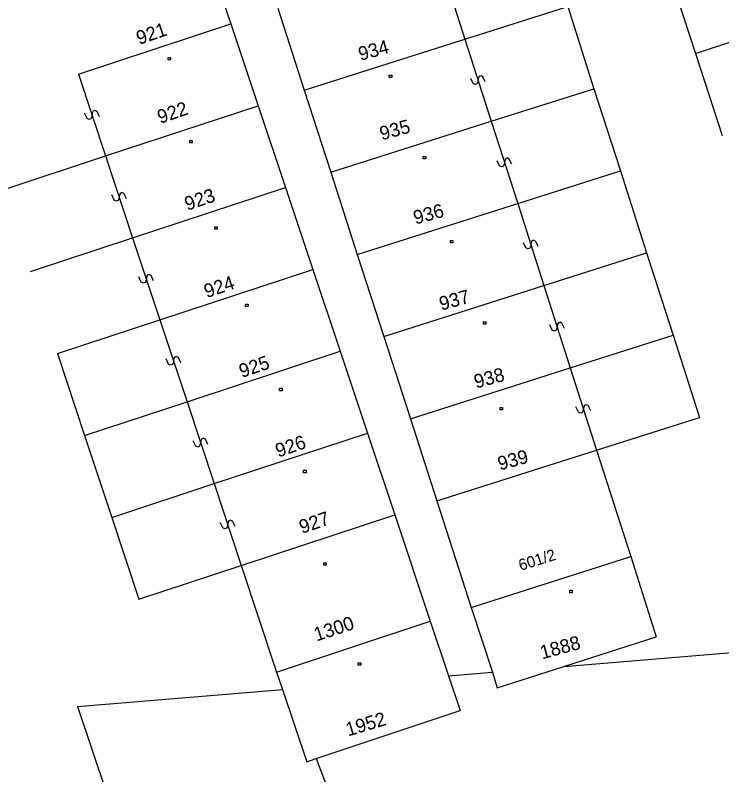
# Model space of a CAD drawing. Extents: x -493352 to -492964, y -1127001 to -1126712.
# Drawn here: x -493295.47 to -493269.27, y -1126768.92 to -1126740.75 of the extents above; entities that cross this region are included whole.
import ezdxf

# ---------------------------------------------------------------- set-up
doc = ezdxf.new("R2010")
doc.units = 0
doc.layers.add('katastrální mapa', color=7, linetype='Continuous')

msp = doc.modelspace()

# ---------------------------------------------------------------- linework, layer by layer
at = {"layer": 'katastrální mapa'}
for p, q in [((-493288.49, -1126738.04), (-493287.48, -1126741.07)), ((-493279.77, -1126738.59), (-493278.8, -1126741.64)), ((-493271.24, -1126739.13), (-493270.25, -1126742.17)), ((-493285.74, -1126740.49), (-493284.76, -1126743.54)), ((-493278.8, -1126741.64), (-493274.98, -1126740.43)), ((-493274.98, -1126740.43), (-493274.01, -1126743.48)), ((-493293.13, -1126742.94), (-493287.48, -1126741.07)), ((-493287.48, -1126741.07), (-493286.46, -1126744.11)), ((-493270.25, -1126742.17), (-493266.45, -1126740.91)), ((-493284.76, -1126743.54), (-493278.8, -1126741.64)), ((-493278.8, -1126741.64), (-493277.82, -1126744.69)), ((-493270.25, -1126742.17), (-493269.26, -1126745.21)), ((-493289.8, -1126742.32), (-493289.71, -1126742.32)), ((-493289.8, -1126742.41), (-493289.8, -1126742.32)), ((-493289.71, -1126742.41), (-493289.8, -1126742.41)), ((-493289.71, -1126742.32), (-493289.71, -1126742.41)), ((-493293.13, -1126742.94), (-493292.12, -1126745.97)), ((-493281.6, -1126742.98), (-493281.51, -1126742.98)), ((-493281.6, -1126743.07), (-493281.6, -1126742.98)), ((-493281.51, -1126743.07), (-493281.6, -1126743.07)), ((-493281.51, -1126742.98), (-493281.51, -1126743.07)), ((-493278.26, -1126743.02), (-493278.3, -1126743.1)), ((-493278.2, -1126743), (-493278.26, -1126743.02)), ((-493278.13, -1126743.04), (-493278.2, -1126743)), ((-493278.04, -1126743.23), (-493278.13, -1126743.04)), ((-493278.49, -1126743.29), (-493278.58, -1126743.1)), ((-493278.42, -1126743.33), (-493278.49, -1126743.29)), ((-493278.36, -1126743.31), (-493278.42, -1126743.33)), ((-493278.32, -1126743.23), (-493278.36, -1126743.31)), ((-493278.3, -1126743.1), (-493278.32, -1126743.23)), ((-493284.76, -1126743.54), (-493283.77, -1126746.58)), ((-493277.82, -1126744.69), (-493274.01, -1126743.48)), ((-493274.01, -1126743.48), (-493273.03, -1126746.53)), ((-493292.12, -1126745.97), (-493286.46, -1126744.11)), ((-493286.46, -1126744.11), (-493285.45, -1126747.14)), ((-493292.81, -1126744.58), (-493292.9, -1126744.39)), ((-493292.62, -1126744.39), (-493292.63, -1126744.52)), ((-493292.58, -1126744.31), (-493292.62, -1126744.39)), ((-493292.52, -1126744.29), (-493292.58, -1126744.31)), ((-493292.44, -1126744.33), (-493292.52, -1126744.29)), ((-493292.35, -1126744.52), (-493292.44, -1126744.33)), ((-493292.73, -1126744.62), (-493292.81, -1126744.58)), ((-493292.67, -1126744.6), (-493292.73, -1126744.62)), ((-493292.63, -1126744.52), (-493292.67, -1126744.6)), ((-493283.77, -1126746.58), (-493277.82, -1126744.69)), ((-493277.82, -1126744.69), (-493276.84, -1126747.74)), ((-493289, -1126745.4), (-493288.91, -1126745.4)), ((-493289, -1126745.49), (-493289, -1126745.4)), ((-493288.91, -1126745.49), (-493289, -1126745.49)), ((-493288.91, -1126745.4), (-493288.91, -1126745.49)), ((-493295.92, -1126747.23), (-493292.12, -1126745.97)), ((-493292.12, -1126745.97), (-493291.12, -1126749.01)), ((-493280.34, -1126745.99), (-493280.25, -1126745.99)), ((-493280.34, -1126746.08), (-493280.34, -1126745.99)), ((-493280.25, -1126746.08), (-493280.34, -1126746.08)), ((-493280.25, -1126745.99), (-493280.25, -1126746.08)), ((-493277.51, -1126746.34), (-493277.6, -1126746.15)), ((-493277.32, -1126746.15), (-493277.34, -1126746.28)), ((-493277.28, -1126746.07), (-493277.32, -1126746.15)), ((-493277.22, -1126746.05), (-493277.28, -1126746.07)), ((-493277.15, -1126746.09), (-493277.22, -1126746.05)), ((-493277.06, -1126746.28), (-493277.15, -1126746.09)), ((-493277.44, -1126746.38), (-493277.51, -1126746.34)), ((-493277.38, -1126746.36), (-493277.44, -1126746.38)), ((-493277.34, -1126746.28), (-493277.38, -1126746.36)), ((-493283.77, -1126746.58), (-493282.79, -1126749.63)), ((-493276.84, -1126747.74), (-493273.03, -1126746.53)), ((-493273.03, -1126746.53), (-493272.06, -1126749.57)), ((-493291.12, -1126749.01), (-493285.45, -1126747.14)), ((-493285.45, -1126747.14), (-493284.44, -1126750.18)), ((-493291.8, -1126747.61), (-493291.89, -1126747.42)), ((-493291.63, -1126747.56), (-493291.67, -1126747.63)), ((-493291.61, -1126747.42), (-493291.63, -1126747.56)), ((-493291.57, -1126747.35), (-493291.61, -1126747.42)), ((-493291.52, -1126747.33), (-493291.57, -1126747.35)), ((-493291.44, -1126747.37), (-493291.52, -1126747.33)), ((-493291.35, -1126747.56), (-493291.44, -1126747.37)), ((-493291.72, -1126747.65), (-493291.8, -1126747.61)), ((-493291.67, -1126747.63), (-493291.72, -1126747.65)), ((-493282.79, -1126749.63), (-493276.84, -1126747.74)), ((-493276.84, -1126747.74), (-493275.87, -1126750.78)), ((-493288.07, -1126748.6), (-493287.98, -1126748.6)), ((-493288.07, -1126748.69), (-493288.07, -1126748.6)), ((-493287.98, -1126748.69), (-493288.07, -1126748.69)), ((-493287.98, -1126748.6), (-493287.98, -1126748.69)), ((-493294.91, -1126750.26), (-493291.12, -1126749.01)), ((-493291.12, -1126749.01), (-493290.11, -1126752.05)), ((-493279.33, -1126749.11), (-493279.24, -1126749.11)), ((-493279.33, -1126749.2), (-493279.33, -1126749.11)), ((-493279.24, -1126749.2), (-493279.33, -1126749.2)), ((-493279.24, -1126749.11), (-493279.24, -1126749.2)), ((-493276.54, -1126749.38), (-493276.63, -1126749.19)), ((-493276.34, -1126749.19), (-493276.37, -1126749.33)), ((-493276.31, -1126749.12), (-493276.34, -1126749.19)), ((-493276.25, -1126749.1), (-493276.31, -1126749.12)), ((-493276.17, -1126749.14), (-493276.25, -1126749.1)), ((-493276.08, -1126749.33), (-493276.17, -1126749.14)), ((-493276.46, -1126749.42), (-493276.54, -1126749.38)), ((-493276.4, -1126749.4), (-493276.46, -1126749.42)), ((-493276.37, -1126749.33), (-493276.4, -1126749.4)), ((-493282.79, -1126749.63), (-493281.8, -1126752.67)), ((-493275.87, -1126750.78), (-493272.06, -1126749.57)), ((-493272.06, -1126749.57), (-493271.08, -1126752.62)), ((-493290.57, -1126750.39), (-493290.61, -1126750.46)), ((-493290.51, -1126750.37), (-493290.57, -1126750.39)), ((-493290.43, -1126750.41), (-493290.51, -1126750.37)), ((-493290.11, -1126752.05), (-493284.44, -1126750.18)), ((-493284.44, -1126750.18), (-493283.42, -1126753.21)), ((-493290.8, -1126750.65), (-493290.89, -1126750.46)), ((-493290.72, -1126750.69), (-493290.8, -1126750.65)), ((-493290.66, -1126750.67), (-493290.72, -1126750.69)), ((-493290.62, -1126750.6), (-493290.66, -1126750.67)), ((-493290.61, -1126750.46), (-493290.62, -1126750.6)), ((-493290.34, -1126750.6), (-493290.43, -1126750.41)), ((-493281.8, -1126752.67), (-493275.87, -1126750.78)), ((-493275.87, -1126750.78), (-493274.89, -1126753.83)), ((-493286.93, -1126751.47), (-493286.84, -1126751.47)), ((-493286.93, -1126751.56), (-493286.93, -1126751.47)), ((-493286.84, -1126751.47), (-493286.84, -1126751.56)), ((-493286.84, -1126751.56), (-493286.93, -1126751.56)), ((-493293.91, -1126753.3), (-493290.11, -1126752.05)), ((-493290.11, -1126752.05), (-493289.1, -1126755.09)), ((-493278.11, -1126752.12), (-493278.02, -1126752.12)), ((-493278.11, -1126752.21), (-493278.11, -1126752.12)), ((-493278.02, -1126752.21), (-493278.11, -1126752.21)), ((-493278.02, -1126752.12), (-493278.02, -1126752.21)), ((-493275.56, -1126752.43), (-493275.65, -1126752.24)), ((-493275.39, -1126752.37), (-493275.43, -1126752.45)), ((-493275.37, -1126752.24), (-493275.39, -1126752.37)), ((-493275.33, -1126752.16), (-493275.37, -1126752.24)), ((-493275.27, -1126752.14), (-493275.33, -1126752.16)), ((-493275.2, -1126752.18), (-493275.27, -1126752.14)), ((-493275.11, -1126752.37), (-493275.2, -1126752.18)), ((-493275.49, -1126752.47), (-493275.56, -1126752.43)), ((-493275.43, -1126752.45), (-493275.49, -1126752.47)), ((-493274.89, -1126753.83), (-493271.08, -1126752.62)), ((-493271.08, -1126752.62), (-493270.1, -1126755.67)), ((-493281.8, -1126752.67), (-493280.82, -1126755.72)), ((-493289.1, -1126755.09), (-493283.42, -1126753.21)), ((-493283.42, -1126753.21), (-493282.41, -1126756.25)), ((-493293.91, -1126753.3), (-493292.9, -1126756.34)), ((-493289.56, -1126753.43), (-493289.6, -1126753.5)), ((-493289.5, -1126753.41), (-493289.56, -1126753.43)), ((-493289.42, -1126753.45), (-493289.5, -1126753.41)), ((-493289.33, -1126753.64), (-493289.42, -1126753.45)), ((-493289.79, -1126753.69), (-493289.88, -1126753.5)), ((-493289.71, -1126753.73), (-493289.79, -1126753.69)), ((-493289.65, -1126753.71), (-493289.71, -1126753.73)), ((-493289.61, -1126753.64), (-493289.65, -1126753.71)), ((-493289.6, -1126753.5), (-493289.61, -1126753.64)), ((-493280.82, -1126755.72), (-493274.89, -1126753.83)), ((-493274.89, -1126753.83), (-493273.92, -1126756.88)), ((-493285.67, -1126754.59), (-493285.58, -1126754.59)), ((-493285.67, -1126754.68), (-493285.67, -1126754.59)), ((-493285.58, -1126754.59), (-493285.58, -1126754.68)), ((-493285.58, -1126754.68), (-493285.67, -1126754.68)), ((-493292.9, -1126756.34), (-493289.1, -1126755.09)), ((-493289.1, -1126755.09), (-493288.1, -1126758.12)), ((-493277.49, -1126755.3), (-493277.4, -1126755.3)), ((-493277.49, -1126755.39), (-493277.49, -1126755.3)), ((-493277.4, -1126755.39), (-493277.49, -1126755.39)), ((-493277.4, -1126755.3), (-493277.4, -1126755.39)), ((-493274.59, -1126755.48), (-493274.68, -1126755.28)), ((-493274.42, -1126755.42), (-493274.45, -1126755.5)), ((-493274.39, -1126755.29), (-493274.42, -1126755.42)), ((-493274.36, -1126755.21), (-493274.39, -1126755.29)), ((-493274.3, -1126755.2), (-493274.36, -1126755.21)), ((-493274.22, -1126755.23), (-493274.3, -1126755.2)), ((-493274.13, -1126755.43), (-493274.22, -1126755.23)), ((-493280.82, -1126755.72), (-493279.84, -1126758.76)), ((-493274.51, -1126755.51), (-493274.59, -1126755.48)), ((-493274.45, -1126755.5), (-493274.51, -1126755.51)), ((-493273.92, -1126756.88), (-493270.1, -1126755.67)), ((-493288.1, -1126758.12), (-493282.41, -1126756.25)), ((-493282.41, -1126756.25), (-493281.4, -1126759.28)), ((-493292.9, -1126756.34), (-493291.89, -1126759.38)), ((-493288.78, -1126756.73), (-493288.87, -1126756.54)), ((-493288.59, -1126756.54), (-493288.61, -1126756.67)), ((-493288.55, -1126756.46), (-493288.59, -1126756.54)), ((-493288.5, -1126756.44), (-493288.55, -1126756.46)), ((-493288.42, -1126756.48), (-493288.5, -1126756.44)), ((-493288.33, -1126756.67), (-493288.42, -1126756.48)), ((-493288.7, -1126756.77), (-493288.78, -1126756.73)), ((-493288.65, -1126756.75), (-493288.7, -1126756.77)), ((-493288.61, -1126756.67), (-493288.65, -1126756.75)), ((-493279.84, -1126758.76), (-493273.92, -1126756.88)), ((-493273.92, -1126756.88), (-493272.65, -1126760.82)), ((-493284.78, -1126757.63), (-493284.69, -1126757.63)), ((-493284.78, -1126757.72), (-493284.78, -1126757.63)), ((-493284.69, -1126757.72), (-493284.78, -1126757.72)), ((-493284.69, -1126757.63), (-493284.69, -1126757.72)), ((-493291.89, -1126759.38), (-493288.1, -1126758.12)), ((-493288.1, -1126758.12), (-493287.09, -1126761.16)), ((-493279.84, -1126758.76), (-493278.56, -1126762.72)), ((-493291.89, -1126759.38), (-493290.89, -1126762.41)), ((-493287.09, -1126761.16), (-493281.4, -1126759.28)), ((-493281.4, -1126759.28), (-493280.08, -1126763.22)), ((-493287.78, -1126759.76), (-493287.87, -1126759.57)), ((-493287.59, -1126759.57), (-493287.6, -1126759.71)), ((-493287.55, -1126759.5), (-493287.59, -1126759.57)), ((-493287.49, -1126759.48), (-493287.55, -1126759.5)), ((-493287.41, -1126759.52), (-493287.49, -1126759.48)), ((-493287.32, -1126759.71), (-493287.41, -1126759.52)), ((-493287.7, -1126759.8), (-493287.78, -1126759.76)), ((-493287.64, -1126759.78), (-493287.7, -1126759.8)), ((-493287.6, -1126759.71), (-493287.64, -1126759.78)), ((-493278.56, -1126762.72), (-493272.65, -1126760.82)), ((-493272.65, -1126760.82), (-493271.7, -1126763.8)), ((-493284.03, -1126761.06), (-493283.94, -1126761.06)), ((-493284.03, -1126761.15), (-493284.03, -1126761.06)), ((-493283.94, -1126761.06), (-493283.94, -1126761.15)), ((-493290.89, -1126762.41), (-493287.09, -1126761.16)), ((-493287.09, -1126761.16), (-493285.78, -1126765.11)), ((-493283.94, -1126761.15), (-493284.03, -1126761.15)), ((-493274.91, -1126762.08), (-493274.82, -1126762.08)), ((-493274.91, -1126762.17), (-493274.91, -1126762.08)), ((-493274.82, -1126762.17), (-493274.91, -1126762.17)), ((-493274.82, -1126762.08), (-493274.82, -1126762.17)), ((-493278.56, -1126762.72), (-493277.78, -1126765.12)), ((-493285.78, -1126765.11), (-493280.08, -1126763.22)), ((-493280.08, -1126763.22), (-493279.4, -1126765.25)), ((-493275.13, -1126764.9), (-493255.66, -1126763.29)), ((-493275.13, -1126764.9), (-493271.7, -1126763.8)), ((-493282.75, -1126764.77), (-493282.66, -1126764.77)), ((-493282.75, -1126764.86), (-493282.75, -1126764.77)), ((-493282.66, -1126764.86), (-493282.75, -1126764.86)), ((-493282.66, -1126764.77), (-493282.66, -1126764.86)), ((-493277.6, -1126765.69), (-493275.13, -1126764.9)), ((-493285.78, -1126765.11), (-493285.56, -1126765.76)), ((-493279.4, -1126765.25), (-493277.78, -1126765.12)), ((-493279.4, -1126765.25), (-493278.97, -1126766.54)), ((-493277.78, -1126765.12), (-493277.6, -1126765.69)), ((-493293.17, -1126766.39), (-493285.56, -1126765.76)), ((-493285.56, -1126765.76), (-493284.66, -1126768.44)), ((-493293.17, -1126766.39), (-493289.51, -1126777.18)), ((-493284.31, -1126768.32), (-493278.97, -1126766.54)), ((-493284.66, -1126768.44), (-493284.31, -1126768.32)), ((-493284.31, -1126768.32), (-493281.85, -1126774.85))]:
    msp.add_line(p, q, dxfattribs=at)

# ---------------------------------------------------------------- texts
for s, height, rotation, p in [('921', 0.51, 18.963, (-493290.88, -1126741.86)), ('934', 0.51, 15.354, (-493282.67, -1126742.45)), ('922', 0.51, 18.963, (-493290.1, -1126744.79)), ('935', 0.51, 15.354, (-493281.88, -1126745.4)), ('923', 0.51, 18.963, (-493289.09, -1126748.01)), ('936', 0.51, 15.354, (-493280.63, -1126748.52)), ('924', 0.51, 18.963, (-493288.37, -1126751.25)), ('937', 0.51, 15.354, (-493279.67, -1126751.71)), ('925', 0.51, 18.963, (-493287.07, -1126754.21)), ('938', 0.51, 15.354, (-493278.38, -1126754.6)), ('926', 0.51, 18.963, (-493285.72, -1126757.16)), ('939', 0.51, 15.354, (-493277.5, -1126757.64)), ('927', 0.51, 18.963, (-493284.84, -1126759.99)), ('601/2', 0.42, 17.478, (-493276.73, -1126761.36)), ('1300', 0.51, 18.279, (-493284.3, -1126763.98)), ('1888', 0.51, 15.354, (-493275.93, -1126764.64)), ('1952', 0.51, 16.677, (-493283.13, -1126767.5))]:
    msp.add_text(s, height=height, rotation=rotation, dxfattribs=at).set_placement(p)

doc.saveas('drawing.dxf')
